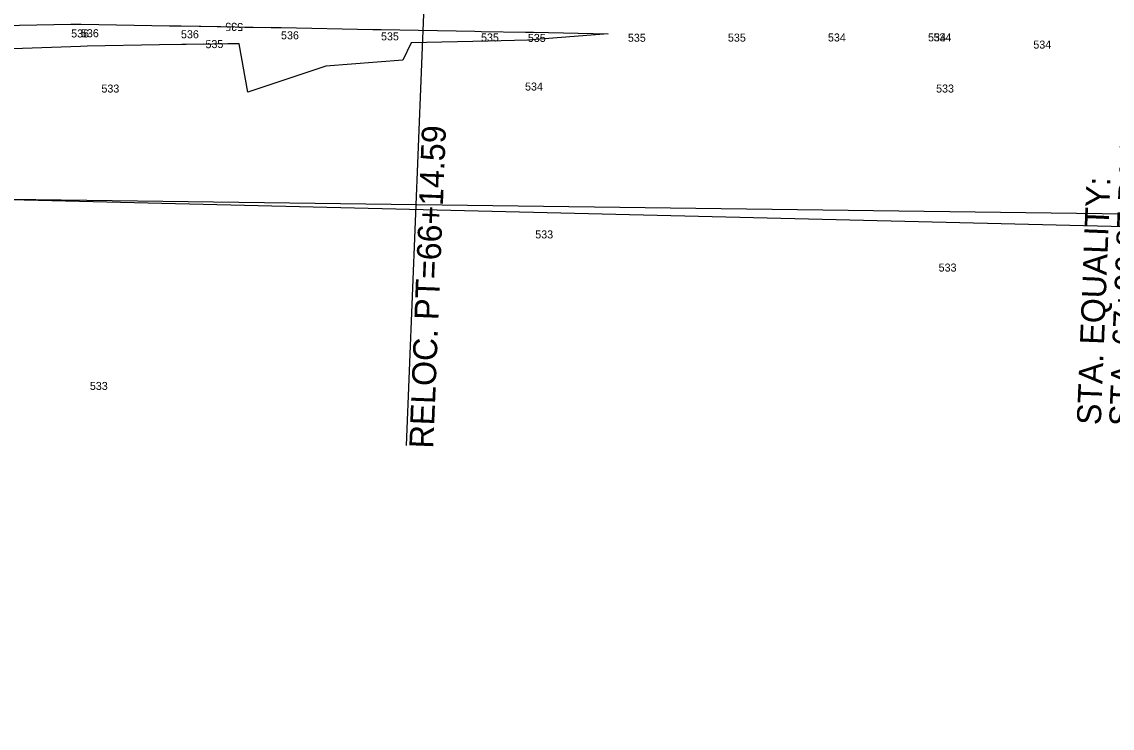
# Model space of a CAD drawing. Extents: x 1787461 to 1970323, y 938412 to 1118748.
# Drawn here: x 1968194.3 to 1968466.8, y 1117714.7 to 1117891.1 of the extents above; entities that cross this region are included whole.
import ezdxf

# ---------------------------------------------------------------- set-up
doc = ezdxf.new("R2010")
doc.units = 0
for name, color, linetype in [('Default', 7, 'Continuous'), ('HHA ADDITIONAL XSs', 7, 'Continuous'), ('Level 1', 7, 'Continuous'), ('RD_HC_CL_Rel', 7, 'Continuous'), ('RD_HC_Data_Rel', 7, 'Continuous'), ('RD_PD_Final_TrvlWay', 7, 'Continuous')]:
    doc.layers.add(name, color=color, linetype=linetype)

msp = doc.modelspace()

# ---------------------------------------------------------------- linework, layer by layer
at = {"layer": 'Default'}
for points in [[(1968045.37, 1117879.84), (1968046.67, 1117880.39), (1968056.53, 1117884.75), (1968057.89, 1117885.33), (1968060.84, 1117885.43), (1968082.82, 1117887.23), (1968101.58, 1117888.76), (1968104.32, 1117888.85), (1968126.26, 1117889.12), (1968129.33, 1117889.23), (1968151.06, 1117889.5), (1968154.33, 1117889.62), (1968156.5, 1117889.65), (1968156.56, 1117889.65), (1968160.12, 1117889.66), (1968181.56, 1117890.1), (1968185.13, 1117890.11), (1968206.55, 1117890.55), (1968207.07, 1117890.55), (1968209.18, 1117890.59), (1968231.23, 1117890.18), (1968234.16, 1117890.14), (1968244.06, 1117889.96)], [(1968045.37, 1117879.84), (1968046.67, 1117880.39), (1968056.53, 1117884.75), (1968057.89, 1117885.33), (1968060.84, 1117885.43), (1968082.82, 1117887.23), (1968101.58, 1117888.76), (1968104.32, 1117888.85), (1968126.26, 1117889.12), (1968129.33, 1117889.23), (1968151.06, 1117889.5), (1968154.33, 1117889.62), (1968156.5, 1117889.65), (1968156.56, 1117889.65), (1968160.12, 1117889.66), (1968181.56, 1117890.1), (1968185.13, 1117890.11), (1968206.55, 1117890.55), (1968207.07, 1117890.55), (1968209.18, 1117890.59), (1968231.23, 1117890.18), (1968234.16, 1117890.14), (1968244.06, 1117889.96)], [(1968045.37, 1117879.84), (1968046.67, 1117880.39), (1968056.53, 1117884.75), (1968057.89, 1117885.33), (1968060.84, 1117885.43), (1968082.82, 1117887.23), (1968101.58, 1117888.76), (1968104.32, 1117888.85), (1968126.26, 1117889.12), (1968129.33, 1117889.23), (1968151.06, 1117889.5), (1968154.33, 1117889.62), (1968156.5, 1117889.65), (1968156.56, 1117889.65), (1968160.12, 1117889.66), (1968181.56, 1117890.1), (1968185.13, 1117890.11), (1968206.55, 1117890.55), (1968207.07, 1117890.55), (1968209.18, 1117890.59), (1968231.23, 1117890.18), (1968234.16, 1117890.14), (1968244.06, 1117889.96)], [(1968045.37, 1117879.84), (1968046.67, 1117880.39), (1968056.53, 1117884.75), (1968057.89, 1117885.33), (1968060.84, 1117885.43), (1968082.82, 1117887.23), (1968101.58, 1117888.76), (1968104.32, 1117888.85), (1968126.26, 1117889.12), (1968129.33, 1117889.23), (1968151.06, 1117889.5), (1968154.33, 1117889.62), (1968156.5, 1117889.65), (1968156.56, 1117889.65), (1968160.12, 1117889.66), (1968181.56, 1117890.1), (1968185.13, 1117890.11), (1968206.55, 1117890.55), (1968207.07, 1117890.55), (1968209.18, 1117890.59), (1968231.23, 1117890.18), (1968234.16, 1117890.14), (1968244.06, 1117889.96)], [(1968045.37, 1117879.84), (1968046.67, 1117880.39), (1968056.53, 1117884.75), (1968057.89, 1117885.33), (1968060.84, 1117885.43), (1968082.82, 1117887.23), (1968101.58, 1117888.76), (1968104.32, 1117888.85), (1968126.26, 1117889.12), (1968129.33, 1117889.23), (1968151.06, 1117889.5), (1968154.33, 1117889.62), (1968156.5, 1117889.65), (1968156.56, 1117889.65), (1968160.12, 1117889.66), (1968181.56, 1117890.1), (1968185.13, 1117890.11), (1968206.55, 1117890.55), (1968207.07, 1117890.55), (1968209.18, 1117890.59), (1968231.23, 1117890.18), (1968234.16, 1117890.14), (1968244.06, 1117889.96)], [(1968045.37, 1117879.84), (1968046.67, 1117880.39), (1968056.53, 1117884.75), (1968057.89, 1117885.33), (1968060.84, 1117885.43), (1968082.82, 1117887.23), (1968101.58, 1117888.76), (1968104.32, 1117888.85), (1968126.26, 1117889.12), (1968129.33, 1117889.23), (1968151.06, 1117889.5), (1968154.33, 1117889.62), (1968156.5, 1117889.65), (1968156.56, 1117889.65), (1968160.12, 1117889.66), (1968181.56, 1117890.1), (1968185.13, 1117890.11), (1968206.55, 1117890.55), (1968207.07, 1117890.55), (1968209.18, 1117890.59), (1968231.23, 1117890.18), (1968234.16, 1117890.14), (1968244.06, 1117889.96)], [(1968185.13, 1117890.11), (1968206.55, 1117890.55), (1968207.07, 1117890.55), (1968209.18, 1117890.59), (1968231.23, 1117890.18), (1968234.16, 1117890.14), (1968256.6, 1117889.72), (1968259.15, 1117889.69), (1968282.03, 1117889.26), (1968284.14, 1117889.23), (1968307.52, 1117888.79), (1968309.13, 1117888.77), (1968320.18, 1117888.56), (1968320.79, 1117888.55), (1968322.23, 1117888.55), (1968340.89, 1117888.16), (1968320.7, 1117886.54), (1968310.83, 1117886.31), (1968291.66, 1117885.88), (1968289.54, 1117881.53), (1968270.26, 1117880.04), (1968250.81, 1117873.59), (1968248.67, 1117885.69), (1968228.71, 1117885.37), (1968210.67, 1117885.08), (1968208.98, 1117885.02), (1968192.08, 1117884.43)], [(1968250.06, 1117889.85), (1968256.6, 1117889.72), (1968259.15, 1117889.69), (1968282.03, 1117889.26), (1968284.14, 1117889.23), (1968307.52, 1117888.79), (1968309.13, 1117888.77), (1968320.18, 1117888.56), (1968320.79, 1117888.55), (1968322.23, 1117888.55), (1968340.89, 1117888.16), (1968320.7, 1117886.54), (1968310.83, 1117886.31), (1968291.66, 1117885.88), (1968289.54, 1117881.53), (1968270.26, 1117880.04), (1968250.81, 1117873.59), (1968248.67, 1117885.69), (1968245.79, 1117885.64)], [(1968250.06, 1117889.85), (1968256.6, 1117889.72), (1968259.15, 1117889.69), (1968282.03, 1117889.26), (1968284.14, 1117889.23), (1968307.52, 1117888.79), (1968309.13, 1117888.77), (1968320.18, 1117888.56), (1968320.79, 1117888.55), (1968322.23, 1117888.55), (1968340.89, 1117888.16), (1968320.7, 1117886.54), (1968310.83, 1117886.31), (1968291.66, 1117885.88), (1968289.54, 1117881.53), (1968270.26, 1117880.04), (1968250.81, 1117873.59), (1968248.67, 1117885.69), (1968245.79, 1117885.64)], [(1968250.06, 1117889.85), (1968256.6, 1117889.72), (1968259.15, 1117889.69), (1968282.03, 1117889.26), (1968284.14, 1117889.23), (1968307.52, 1117888.79), (1968309.13, 1117888.77), (1968320.18, 1117888.56), (1968320.79, 1117888.55), (1968322.23, 1117888.55), (1968340.89, 1117888.16), (1968320.7, 1117886.54), (1968310.83, 1117886.31), (1968291.66, 1117885.88), (1968289.54, 1117881.53), (1968270.26, 1117880.04), (1968250.81, 1117873.59), (1968248.67, 1117885.69), (1968245.79, 1117885.64)], [(1968250.06, 1117889.85), (1968256.6, 1117889.72), (1968259.15, 1117889.69), (1968282.03, 1117889.26), (1968284.14, 1117889.23), (1968307.52, 1117888.79), (1968309.13, 1117888.77), (1968320.18, 1117888.56), (1968320.79, 1117888.55), (1968322.23, 1117888.55), (1968340.89, 1117888.16), (1968320.7, 1117886.54), (1968310.83, 1117886.31), (1968291.66, 1117885.88), (1968289.54, 1117881.53), (1968270.26, 1117880.04), (1968250.81, 1117873.59), (1968248.67, 1117885.69), (1968245.79, 1117885.64)], [(1968250.06, 1117889.85), (1968256.6, 1117889.72), (1968259.15, 1117889.69), (1968282.03, 1117889.26), (1968284.14, 1117889.23), (1968307.52, 1117888.79), (1968309.13, 1117888.77), (1968320.18, 1117888.56), (1968320.79, 1117888.55), (1968322.23, 1117888.55), (1968340.89, 1117888.16), (1968320.7, 1117886.54), (1968310.83, 1117886.31), (1968291.66, 1117885.88), (1968289.54, 1117881.53), (1968270.26, 1117880.04), (1968250.81, 1117873.59), (1968248.67, 1117885.69), (1968245.79, 1117885.64)], [(1968250.06, 1117889.85), (1968256.6, 1117889.72), (1968259.15, 1117889.69), (1968282.03, 1117889.26), (1968284.14, 1117889.23), (1968307.52, 1117888.79), (1968309.13, 1117888.77), (1968320.18, 1117888.56), (1968320.79, 1117888.55), (1968322.23, 1117888.55), (1968340.89, 1117888.16), (1968320.7, 1117886.54), (1968310.83, 1117886.31), (1968291.66, 1117885.88), (1968289.54, 1117881.53), (1968270.26, 1117880.04), (1968250.81, 1117873.59), (1968248.67, 1117885.69), (1968245.79, 1117885.64)], [(1968239.79, 1117885.55), (1968228.71, 1117885.37), (1968210.67, 1117885.08), (1968208.98, 1117885.02), (1968192.08, 1117884.43), (1968174.44, 1117879.51), (1968157.16, 1117878.75), (1968155.46, 1117878.75), (1968138.21, 1117878.81), (1968119.63, 1117880.98), (1968105.61, 1117880.98), (1968093.56, 1117879.97), (1968077.23, 1117871.58), (1968063.17, 1117864.88), (1968057.84, 1117865.45), (1968044.39, 1117863.46)], [(1968239.79, 1117885.55), (1968228.71, 1117885.37), (1968210.67, 1117885.08), (1968208.98, 1117885.02), (1968192.08, 1117884.43), (1968174.44, 1117879.51), (1968157.16, 1117878.75), (1968155.46, 1117878.75), (1968138.21, 1117878.81), (1968119.63, 1117880.98), (1968105.61, 1117880.98), (1968093.56, 1117879.97), (1968077.23, 1117871.58), (1968063.17, 1117864.88), (1968057.84, 1117865.45), (1968044.39, 1117863.46)], [(1968239.79, 1117885.55), (1968228.71, 1117885.37), (1968210.67, 1117885.08), (1968208.98, 1117885.02), (1968192.08, 1117884.43), (1968174.44, 1117879.51), (1968157.16, 1117878.75), (1968155.46, 1117878.75), (1968138.21, 1117878.81), (1968119.63, 1117880.98), (1968105.61, 1117880.98), (1968093.56, 1117879.97), (1968077.23, 1117871.58), (1968063.17, 1117864.88), (1968057.84, 1117865.45), (1968044.39, 1117863.46)], [(1968239.79, 1117885.55), (1968228.71, 1117885.37), (1968210.67, 1117885.08), (1968208.98, 1117885.02), (1968192.08, 1117884.43), (1968174.44, 1117879.51), (1968157.16, 1117878.75), (1968155.46, 1117878.75), (1968138.21, 1117878.81), (1968119.63, 1117880.98), (1968105.61, 1117880.98), (1968093.56, 1117879.97), (1968077.23, 1117871.58), (1968063.17, 1117864.88), (1968057.84, 1117865.45), (1968044.39, 1117863.46)], [(1968239.79, 1117885.55), (1968228.71, 1117885.37), (1968210.67, 1117885.08), (1968208.98, 1117885.02), (1968192.08, 1117884.43), (1968174.44, 1117879.51), (1968157.16, 1117878.75), (1968155.46, 1117878.75), (1968138.21, 1117878.81), (1968119.63, 1117880.98), (1968105.61, 1117880.98), (1968093.56, 1117879.97), (1968077.23, 1117871.58), (1968063.17, 1117864.88), (1968057.84, 1117865.45), (1968044.39, 1117863.46)], [(1968239.79, 1117885.55), (1968228.71, 1117885.37), (1968210.67, 1117885.08), (1968208.98, 1117885.02), (1968192.08, 1117884.43), (1968174.44, 1117879.51), (1968157.16, 1117878.75), (1968155.46, 1117878.75), (1968138.21, 1117878.81), (1968119.63, 1117880.98), (1968105.61, 1117880.98), (1968093.56, 1117879.97), (1968077.23, 1117871.58), (1968063.17, 1117864.88), (1968057.84, 1117865.45), (1968044.39, 1117863.46)]]:
    msp.add_lwpolyline(points, dxfattribs=at)
at = {"layer": 'HHA ADDITIONAL XSs'}
msp.add_lwpolyline([(1969308.89, 1117819.66), (1967912.94, 1117853.44), (1967442.55, 1117653.93), (1967107.32, 1117508.48)], dxfattribs=at)
for radius in [1667.02, 1607.02]:
    msp.add_arc((1968231.34, 1116297.54), radius, 87.72663, 111.99584, dxfattribs=at)
at = {"layer": 'Level 1'}
msp.add_lwpolyline([(1968654.57, 1117840.68), (1968058.24, 1117848.48), (1967686.38, 1117740.3), (1966964.76, 1117453.35)], dxfattribs=at)
at = {"layer": 'RD_HC_CL_Rel'}
msp.add_arc((1968231.34, 1116297.54), 1637.02, 87.72663, 111.99584, dxfattribs=at)
at = {"layer": 'RD_HC_Data_Rel'}
msp.add_line((1968296.28, 1117933.27), (1968290.41, 1117785.35), dxfattribs=at)
at = {"layer": 'RD_PD_Final_TrvlWay'}
for radius in [1648.02, 1626.02]:
    msp.add_arc((1968231.34, 1116297.54), radius, 87.72663, 111.99584, dxfattribs=at)

# ---------------------------------------------------------------- texts
at = {"layer": 'Default'}
for rotation, p in [(178.9312, (1968249.65, 1117890.85)), (178.9312, (1968249.65, 1117890.85)), (178.9312, (1968249.65, 1117890.85)), (178.9312, (1968249.65, 1117890.85)), (178.9312, (1968249.65, 1117890.85)), (178.9312, (1968249.65, 1117890.85)), (0.924, (1968240.23, 1117884.55)), (0.924, (1968240.23, 1117884.55)), (0.924, (1968240.23, 1117884.55)), (0.924, (1968240.23, 1117884.55)), (0.924, (1968240.23, 1117884.55)), (0.924, (1968240.23, 1117884.55))]:
    msp.add_text('535', height=2, rotation=rotation, dxfattribs=at).set_placement(p)
for s, p in [('536', (1968206.65, 1117887.24)), ('536', (1968209.1, 1117887.3)), ('536', (1968234.1, 1117887.04)), ('536', (1968259.1, 1117886.78)), ('535', (1968284.09, 1117886.52)), ('535', (1968309.09, 1117886.25)), ('535', (1968320.79, 1117886.13)), ('535', (1968345.79, 1117886.17)), ('535', (1968370.79, 1117886.2)), ('534', (1968395.79, 1117886.24)), ('534', (1968420.79, 1117886.27)), ('534', (1968422.17, 1117886.28)), ('534', (1968447.11, 1117884.46)), ('534', (1968320.08, 1117873.98)), ('533', (1968214.22, 1117873.48)), ('533', (1968422.81, 1117873.49)), ('533', (1968322.64, 1117837.05)), ('533', (1968423.45, 1117828.77)), ('533', (1968211.33, 1117799.21))]:
    msp.add_text(s, height=2, dxfattribs=at).set_placement(p)
at = {"layer": 'RD_HC_Data_Rel'}
for s, p in [('STA. 67+96.87 BACK = ', (1968472.03, 1117790.05)), ('RELOC. PT=66+14.59', (1968297.14, 1117784.5)), ('STA. EQUALITY:', (1968463.96, 1117790.37))]:
    msp.add_text(s, height=6, rotation=87.7266, dxfattribs=at).set_placement(p)

doc.saveas('drawing.dxf')
